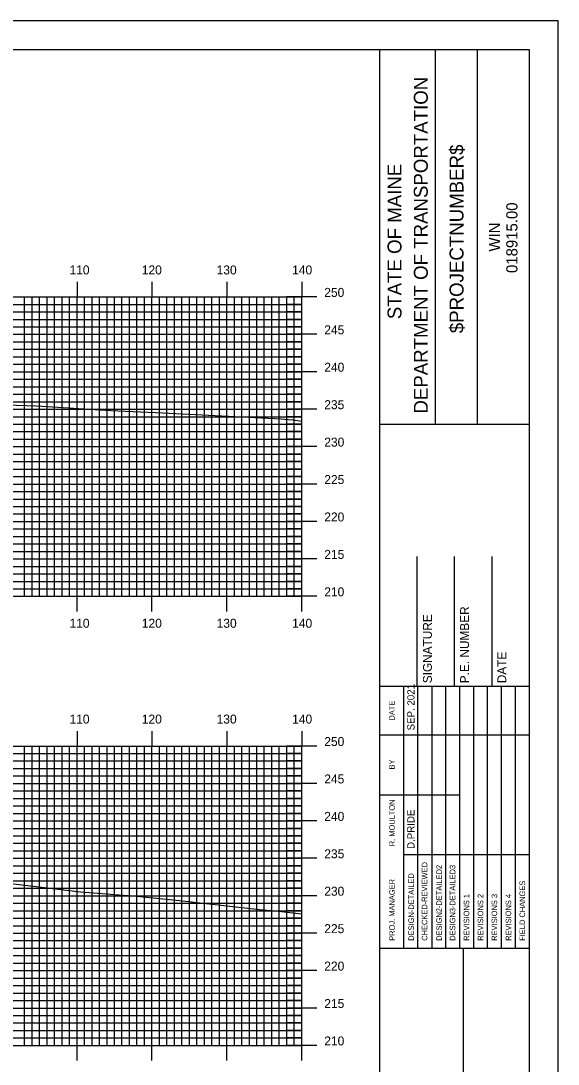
# Model space of a CAD drawing. Extents: x 1816489 to 1816833, y 442591 to 442811.
# Drawn here: x 1816757.6 to 1816829.3, y 442671.2 to 442810.5 of the extents above; entities that cross this region are included whole.
import ezdxf

# ---------------------------------------------------------------- set-up
doc = ezdxf.new("R2010")
doc.units = 0
for name, color, linetype in [('BORDER', 7, 'Continuous'), ('H_V ANNOTATION', 7, 'Continuous'), ('MAJOR', 7, 'Continuous'), ('MINOR', 7, 'Continuous'), ('PLOT BOUNDARY', 7, 'Continuous'), ('S_Roadway_Centerline', 7, 'Continuous')]:
    doc.layers.add(name, color=color, linetype=linetype)

msp = doc.modelspace()

# ---------------------------------------------------------------- linework, layer by layer
at = {"layer": 'BORDER'}
for p, q in [((1816805.47, 442596.67), (1816805.47, 442806.67)), ((1816812.93, 442756.66), (1816812.93, 442806.66)), ((1816818.52, 442756.66), (1816818.52, 442806.66)), ((1816805.47, 442756.65), (1816825.47, 442756.65)), ((1816810.47, 442721.67), (1816810.47, 442738.97)), ((1816815.47, 442721.67), (1816815.47, 442738.97)), ((1816820.47, 442721.67), (1816820.47, 442738.97)), ((1816805.47, 442721.67), (1816825.47, 442721.67)), ((1816805.47, 442686.67), (1816825.47, 442686.67)), ((1816816.66, 442616.67), (1816816.66, 442686.67))]:
    msp.add_line(p, q, dxfattribs=at)
msp.add_lwpolyline([(1816505.47, 442596.67), (1816825.47, 442596.67), (1816825.47, 442806.67), (1816505.47, 442806.67)], close=True, dxfattribs=at)
for points in [[(1816808.7, 442715.17), (1816808.7, 442721.67)], [(1816810.57, 442686.68), (1816810.57, 442721.67)], [(1816812.43, 442721.67), (1816812.43, 442686.68)], [(1816814.29, 442686.68), (1816814.29, 442721.67)], [(1816816.16, 442686.68), (1816816.16, 442721.67)], [(1816818.02, 442686.68), (1816818.02, 442721.67)], [(1816819.88, 442686.68), (1816819.88, 442721.67)], [(1816821.75, 442686.68), (1816821.75, 442721.67)], [(1816823.61, 442686.68), (1816823.61, 442721.67)], [(1816808.7, 442686.68), (1816808.7, 442720.26)], [(1816805.47, 442715.17), (1816825.47, 442715.17)], [(1816805.47, 442707.17), (1816808.7, 442707.17)], [(1816808.7, 442707.17), (1816816.16, 442707.17)], [(1816808.7, 442699.17), (1816825.47, 442699.17)]]:
    msp.add_lwpolyline(points, dxfattribs=at)
at = {"layer": 'MAJOR'}
for p, q in [((1816765.07, 442775.67), (1816765.07, 442773.67)), ((1816775.07, 442775.67), (1816775.07, 442773.67)), ((1816785.07, 442775.67), (1816785.07, 442773.67)), ((1816795.07, 442775.67), (1816795.07, 442773.67)), ((1816515.07, 442773.67), (1816795.07, 442773.67)), ((1816515.07, 442773.67), (1816795.07, 442773.67)), ((1816765.07, 442733.67), (1816765.07, 442773.67)), ((1816775.07, 442733.67), (1816775.07, 442773.67)), ((1816785.07, 442733.67), (1816785.07, 442773.67)), ((1816797.08, 442773.67), (1816793.07, 442773.67)), ((1816795.07, 442733.67), (1816795.07, 442773.67)), ((1816795.07, 442733.67), (1816795.07, 442773.67)), ((1816515.07, 442768.67), (1816795.07, 442768.67)), ((1816797.08, 442768.67), (1816793.07, 442768.67)), ((1816515.07, 442763.67), (1816795.07, 442763.67)), ((1816797.08, 442763.67), (1816793.07, 442763.67)), ((1816515.07, 442758.67), (1816795.07, 442758.67)), ((1816797.08, 442758.67), (1816793.07, 442758.67)), ((1816515.07, 442753.67), (1816795.07, 442753.67)), ((1816797.08, 442753.67), (1816793.07, 442753.67)), ((1816515.07, 442748.67), (1816795.07, 442748.67)), ((1816797.08, 442748.67), (1816793.07, 442748.67)), ((1816515.07, 442743.67), (1816795.07, 442743.67)), ((1816797.08, 442743.67), (1816793.07, 442743.67)), ((1816515.07, 442738.67), (1816795.07, 442738.67)), ((1816797.08, 442738.67), (1816793.07, 442738.67)), ((1816515.07, 442733.67), (1816795.07, 442733.67)), ((1816515.07, 442733.67), (1816795.07, 442733.67)), ((1816765.07, 442731.66), (1816765.07, 442733.67)), ((1816775.07, 442731.66), (1816775.07, 442733.67)), ((1816785.07, 442731.66), (1816785.07, 442733.67)), ((1816797.08, 442733.67), (1816793.07, 442733.67)), ((1816795.07, 442731.66), (1816795.07, 442733.67)), ((1816765.07, 442715.67), (1816765.07, 442713.67)), ((1816775.07, 442715.67), (1816775.07, 442713.67)), ((1816785.07, 442715.67), (1816785.07, 442713.67)), ((1816795.07, 442715.67), (1816795.07, 442713.67)), ((1816515.07, 442713.67), (1816795.07, 442713.67)), ((1816515.07, 442713.67), (1816795.07, 442713.67)), ((1816765.07, 442673.67), (1816765.07, 442713.67)), ((1816775.07, 442673.67), (1816775.07, 442713.67)), ((1816785.07, 442673.67), (1816785.07, 442713.67)), ((1816797.08, 442713.67), (1816793.07, 442713.67)), ((1816795.07, 442673.67), (1816795.07, 442713.67)), ((1816795.07, 442673.67), (1816795.07, 442713.67)), ((1816515.07, 442708.67), (1816795.07, 442708.67)), ((1816797.08, 442708.67), (1816793.07, 442708.67)), ((1816515.07, 442703.67), (1816795.07, 442703.67)), ((1816797.08, 442703.67), (1816793.07, 442703.67)), ((1816515.07, 442698.67), (1816795.07, 442698.67)), ((1816797.08, 442698.67), (1816793.07, 442698.67)), ((1816515.07, 442693.67), (1816795.07, 442693.67)), ((1816797.08, 442693.67), (1816793.07, 442693.67)), ((1816515.07, 442688.67), (1816795.07, 442688.67)), ((1816797.08, 442688.67), (1816793.07, 442688.67)), ((1816515.07, 442683.67), (1816795.07, 442683.67)), ((1816797.08, 442683.67), (1816793.07, 442683.67)), ((1816515.07, 442678.67), (1816795.07, 442678.67)), ((1816797.08, 442678.67), (1816793.07, 442678.67)), ((1816515.07, 442673.67), (1816795.07, 442673.67)), ((1816515.07, 442673.67), (1816795.07, 442673.67)), ((1816765.07, 442671.66), (1816765.07, 442673.67)), ((1816775.07, 442671.66), (1816775.07, 442673.67)), ((1816785.07, 442671.66), (1816785.07, 442673.67)), ((1816797.08, 442673.67), (1816793.07, 442673.67)), ((1816795.07, 442671.66), (1816795.07, 442673.67))]:
    msp.add_line(p, q, dxfattribs=at)
at = {"layer": 'MINOR'}
for p, q in [((1816758.07, 442733.67), (1816758.07, 442773.67)), ((1816759.07, 442733.67), (1816759.07, 442773.67)), ((1816760.07, 442733.67), (1816760.07, 442773.67)), ((1816761.07, 442733.67), (1816761.07, 442773.67)), ((1816762.07, 442733.67), (1816762.07, 442773.67)), ((1816763.07, 442733.67), (1816763.07, 442773.67)), ((1816764.07, 442733.67), (1816764.07, 442773.67)), ((1816766.07, 442733.67), (1816766.07, 442773.67)), ((1816767.07, 442733.67), (1816767.07, 442773.67)), ((1816768.07, 442733.67), (1816768.07, 442773.67)), ((1816769.07, 442733.67), (1816769.07, 442773.67)), ((1816770.07, 442733.67), (1816770.07, 442773.67)), ((1816771.07, 442733.67), (1816771.07, 442773.67)), ((1816772.07, 442733.67), (1816772.07, 442773.67)), ((1816773.07, 442733.67), (1816773.07, 442773.67)), ((1816774.07, 442733.67), (1816774.07, 442773.67)), ((1816776.07, 442733.67), (1816776.07, 442773.67)), ((1816777.07, 442733.67), (1816777.07, 442773.67)), ((1816778.07, 442733.67), (1816778.07, 442773.67)), ((1816779.07, 442733.67), (1816779.07, 442773.67)), ((1816780.07, 442733.67), (1816780.07, 442773.67)), ((1816781.07, 442733.67), (1816781.07, 442773.67)), ((1816782.07, 442733.67), (1816782.07, 442773.67)), ((1816783.07, 442733.67), (1816783.07, 442773.67)), ((1816784.07, 442733.67), (1816784.07, 442773.67)), ((1816786.07, 442733.67), (1816786.07, 442773.67)), ((1816787.07, 442733.67), (1816787.07, 442773.67)), ((1816788.07, 442733.67), (1816788.07, 442773.67)), ((1816789.07, 442733.67), (1816789.07, 442773.67)), ((1816790.07, 442733.67), (1816790.07, 442773.67)), ((1816791.07, 442733.67), (1816791.07, 442773.67)), ((1816792.07, 442733.67), (1816792.07, 442773.67)), ((1816793.07, 442733.67), (1816793.07, 442773.67)), ((1816794.07, 442733.67), (1816794.07, 442773.67)), ((1816515.07, 442772.67), (1816795.07, 442772.67)), ((1816515.07, 442771.67), (1816795.07, 442771.67)), ((1816795.07, 442772.67), (1816793.07, 442772.67)), ((1816795.07, 442771.67), (1816793.07, 442771.67)), ((1816515.07, 442770.67), (1816795.07, 442770.67)), ((1816795.07, 442770.67), (1816793.07, 442770.67)), ((1816515.07, 442769.67), (1816795.07, 442769.67)), ((1816795.07, 442769.67), (1816793.07, 442769.67)), ((1816515.07, 442767.67), (1816795.07, 442767.67)), ((1816795.07, 442767.67), (1816793.07, 442767.67)), ((1816515.07, 442766.67), (1816795.07, 442766.67)), ((1816795.07, 442766.67), (1816793.07, 442766.67)), ((1816515.07, 442765.67), (1816795.07, 442765.67)), ((1816515.07, 442764.67), (1816795.07, 442764.67)), ((1816795.07, 442765.67), (1816793.07, 442765.67)), ((1816795.07, 442764.67), (1816793.07, 442764.67)), ((1816515.07, 442762.67), (1816795.07, 442762.67)), ((1816515.07, 442761.67), (1816795.07, 442761.67)), ((1816795.07, 442762.67), (1816793.07, 442762.67)), ((1816795.07, 442761.67), (1816793.07, 442761.67)), ((1816515.07, 442760.67), (1816795.07, 442760.67)), ((1816795.07, 442760.67), (1816793.07, 442760.67)), ((1816515.07, 442759.67), (1816795.07, 442759.67)), ((1816795.07, 442759.67), (1816793.07, 442759.67)), ((1816515.07, 442757.67), (1816795.07, 442757.67)), ((1816795.07, 442757.67), (1816793.07, 442757.67)), ((1816515.07, 442756.67), (1816795.07, 442756.67)), ((1816795.07, 442756.67), (1816793.07, 442756.67)), ((1816515.07, 442755.67), (1816795.07, 442755.67)), ((1816515.07, 442754.67), (1816795.07, 442754.67)), ((1816795.07, 442755.67), (1816793.07, 442755.67)), ((1816795.07, 442754.67), (1816793.07, 442754.67)), ((1816515.07, 442752.67), (1816795.07, 442752.67)), ((1816795.07, 442752.67), (1816793.07, 442752.67)), ((1816515.07, 442751.67), (1816795.07, 442751.67)), ((1816515.07, 442750.67), (1816795.07, 442750.67)), ((1816795.07, 442751.67), (1816793.07, 442751.67)), ((1816795.07, 442750.67), (1816793.07, 442750.67)), ((1816515.07, 442749.67), (1816795.07, 442749.67)), ((1816795.07, 442749.67), (1816793.07, 442749.67)), ((1816515.07, 442747.67), (1816795.07, 442747.67)), ((1816795.07, 442747.67), (1816793.07, 442747.67)), ((1816515.07, 442746.67), (1816795.07, 442746.67)), ((1816795.07, 442746.67), (1816793.07, 442746.67)), ((1816515.07, 442745.67), (1816795.07, 442745.67)), ((1816795.07, 442745.67), (1816793.07, 442745.67)), ((1816515.07, 442744.67), (1816795.07, 442744.67)), ((1816795.07, 442744.67), (1816793.07, 442744.67)), ((1816515.07, 442742.67), (1816795.07, 442742.67)), ((1816795.07, 442742.67), (1816793.07, 442742.67)), ((1816515.07, 442741.67), (1816795.07, 442741.67)), ((1816795.07, 442741.67), (1816793.07, 442741.67)), ((1816515.07, 442740.67), (1816795.07, 442740.67)), ((1816515.07, 442739.67), (1816795.07, 442739.67)), ((1816795.07, 442740.67), (1816793.07, 442740.67)), ((1816795.07, 442739.67), (1816793.07, 442739.67)), ((1816515.07, 442737.67), (1816795.07, 442737.67)), ((1816515.07, 442736.67), (1816795.07, 442736.67)), ((1816795.07, 442737.67), (1816793.07, 442737.67)), ((1816795.07, 442736.67), (1816793.07, 442736.67)), ((1816515.07, 442735.67), (1816795.07, 442735.67)), ((1816795.07, 442735.67), (1816793.07, 442735.67)), ((1816515.07, 442734.67), (1816795.07, 442734.67)), ((1816795.07, 442734.67), (1816793.07, 442734.67)), ((1816758.07, 442673.67), (1816758.07, 442713.67)), ((1816759.07, 442673.67), (1816759.07, 442713.67)), ((1816760.07, 442673.67), (1816760.07, 442713.67)), ((1816761.07, 442673.67), (1816761.07, 442713.67)), ((1816762.07, 442673.67), (1816762.07, 442713.67)), ((1816763.07, 442673.67), (1816763.07, 442713.67)), ((1816764.07, 442673.67), (1816764.07, 442713.67)), ((1816766.07, 442673.67), (1816766.07, 442713.67)), ((1816767.07, 442673.67), (1816767.07, 442713.67)), ((1816768.07, 442673.67), (1816768.07, 442713.67)), ((1816769.07, 442673.67), (1816769.07, 442713.67)), ((1816770.07, 442673.67), (1816770.07, 442713.67)), ((1816771.07, 442673.67), (1816771.07, 442713.67)), ((1816772.07, 442673.67), (1816772.07, 442713.67)), ((1816773.07, 442673.67), (1816773.07, 442713.67)), ((1816774.07, 442673.67), (1816774.07, 442713.67)), ((1816776.07, 442673.67), (1816776.07, 442713.67)), ((1816777.07, 442673.67), (1816777.07, 442713.67)), ((1816778.07, 442673.67), (1816778.07, 442713.67)), ((1816779.07, 442673.67), (1816779.07, 442713.67)), ((1816780.07, 442673.67), (1816780.07, 442713.67)), ((1816781.07, 442673.67), (1816781.07, 442713.67)), ((1816782.07, 442673.67), (1816782.07, 442713.67)), ((1816783.07, 442673.67), (1816783.07, 442713.67)), ((1816784.07, 442673.67), (1816784.07, 442713.67)), ((1816786.07, 442673.67), (1816786.07, 442713.67)), ((1816787.07, 442673.67), (1816787.07, 442713.67)), ((1816788.07, 442673.67), (1816788.07, 442713.67)), ((1816789.07, 442673.67), (1816789.07, 442713.67)), ((1816790.07, 442673.67), (1816790.07, 442713.67)), ((1816791.07, 442673.67), (1816791.07, 442713.67)), ((1816792.07, 442673.67), (1816792.07, 442713.67)), ((1816793.07, 442673.67), (1816793.07, 442713.67)), ((1816794.07, 442673.67), (1816794.07, 442713.67)), ((1816515.07, 442712.67), (1816795.07, 442712.67)), ((1816515.07, 442711.67), (1816795.07, 442711.67)), ((1816795.07, 442712.67), (1816793.07, 442712.67)), ((1816795.07, 442711.67), (1816793.07, 442711.67)), ((1816515.07, 442710.67), (1816795.07, 442710.67)), ((1816795.07, 442710.67), (1816793.07, 442710.67)), ((1816515.07, 442709.67), (1816795.07, 442709.67)), ((1816795.07, 442709.67), (1816793.07, 442709.67)), ((1816515.07, 442707.67), (1816795.07, 442707.67)), ((1816795.07, 442707.67), (1816793.07, 442707.67)), ((1816515.07, 442706.67), (1816795.07, 442706.67)), ((1816795.07, 442706.67), (1816793.07, 442706.67)), ((1816515.07, 442705.67), (1816795.07, 442705.67)), ((1816515.07, 442704.67), (1816795.07, 442704.67)), ((1816795.07, 442705.67), (1816793.07, 442705.67)), ((1816795.07, 442704.67), (1816793.07, 442704.67)), ((1816515.07, 442702.67), (1816795.07, 442702.67)), ((1816515.07, 442701.67), (1816795.07, 442701.67)), ((1816795.07, 442702.67), (1816793.07, 442702.67)), ((1816795.07, 442701.67), (1816793.07, 442701.67)), ((1816515.07, 442700.67), (1816795.07, 442700.67)), ((1816795.07, 442700.67), (1816793.07, 442700.67)), ((1816515.07, 442699.67), (1816795.07, 442699.67)), ((1816795.07, 442699.67), (1816793.07, 442699.67)), ((1816515.07, 442697.67), (1816795.07, 442697.67)), ((1816795.07, 442697.67), (1816793.07, 442697.67)), ((1816515.07, 442696.67), (1816795.07, 442696.67)), ((1816795.07, 442696.67), (1816793.07, 442696.67)), ((1816515.07, 442695.67), (1816795.07, 442695.67)), ((1816795.07, 442695.67), (1816793.07, 442695.67)), ((1816515.07, 442694.67), (1816795.07, 442694.67)), ((1816795.07, 442694.67), (1816793.07, 442694.67)), ((1816515.07, 442692.67), (1816795.07, 442692.67)), ((1816795.07, 442692.67), (1816793.07, 442692.67)), ((1816515.07, 442691.67), (1816795.07, 442691.67)), ((1816515.07, 442690.67), (1816795.07, 442690.67)), ((1816795.07, 442691.67), (1816793.07, 442691.67)), ((1816795.07, 442690.67), (1816793.07, 442690.67)), ((1816515.07, 442689.67), (1816795.07, 442689.67)), ((1816795.07, 442689.67), (1816793.07, 442689.67)), ((1816515.07, 442687.67), (1816795.07, 442687.67)), ((1816515.07, 442686.67), (1816795.07, 442686.67)), ((1816795.07, 442687.67), (1816793.07, 442687.67)), ((1816795.07, 442686.67), (1816793.07, 442686.67)), ((1816515.07, 442685.67), (1816795.07, 442685.67)), ((1816795.07, 442685.67), (1816793.07, 442685.67)), ((1816515.07, 442684.67), (1816795.07, 442684.67)), ((1816795.07, 442684.67), (1816793.07, 442684.67)), ((1816515.07, 442682.67), (1816795.07, 442682.67)), ((1816795.07, 442682.67), (1816793.07, 442682.67)), ((1816515.07, 442681.67), (1816795.07, 442681.67)), ((1816795.07, 442681.67), (1816793.07, 442681.67)), ((1816515.07, 442680.67), (1816795.07, 442680.67)), ((1816515.07, 442679.67), (1816795.07, 442679.67)), ((1816795.07, 442680.67), (1816793.07, 442680.67)), ((1816795.07, 442679.67), (1816793.07, 442679.67)), ((1816515.07, 442677.67), (1816795.07, 442677.67)), ((1816515.07, 442676.67), (1816795.07, 442676.67)), ((1816795.07, 442677.67), (1816793.07, 442677.67)), ((1816795.07, 442676.67), (1816793.07, 442676.67)), ((1816515.07, 442675.67), (1816795.07, 442675.67)), ((1816795.07, 442675.67), (1816793.07, 442675.67)), ((1816515.07, 442674.67), (1816795.07, 442674.67)), ((1816795.07, 442674.67), (1816793.07, 442674.67))]:
    msp.add_line(p, q, dxfattribs=at)
at = {"layer": 'PLOT BOUNDARY'}
msp.add_lwpolyline([(1816489.29, 442590.55), (1816829.29, 442590.55), (1816829.29, 442810.55), (1816489.29, 442810.55)], close=True, dxfattribs=at)
at = {"layer": 'S_Roadway_Centerline'}
for points in [[(1816684.67, 442763.38), (1816688.54, 442763.29), (1816690.96, 442763.15), (1816693.6, 442762.92), (1816696.97, 442762.92), (1816709.06, 442761.95), (1816724.24, 442761.08), (1816725.42, 442761), (1816730.22, 442760.64), (1816740.26, 442759.88), (1816741.95, 442759.77), (1816744.76, 442759.61), (1816759.65, 442759.11), (1816769.56, 442758.48), (1816776.48, 442758.16), (1816792.33, 442757.36), (1816793.3, 442757.27), (1816793.89, 442757.24), (1816795.07, 442757.09)], [(1816678.58, 442701.01), (1816690.94, 442700.24), (1816693.32, 442700.75), (1816695.45, 442699.98), (1816698.67, 442699.81), (1816701.63, 442699.46), (1816703.64, 442699.27), (1816704.72, 442699.13), (1816716.67, 442698.53), (1816721.45, 442698.19), (1816724.58, 442698.06), (1816734.94, 442697.24), (1816738.44, 442696.94), (1816739.5, 442696.86), (1816752.33, 442695.86), (1816756.62, 442695.24), (1816765.53, 442694.2), (1816772.99, 442693.6), (1816778.73, 442693.04), (1816789.41, 442691.82), (1816791.91, 442691.6), (1816795.07, 442691.25)]]:
    msp.add_lwpolyline(points, dxfattribs=at)

# ---------------------------------------------------------------- texts
at = {"layer": 'BORDER'}
for s, height, p in [('DEPARTMENT OF TRANSPORTATION', 1.8635, (1816811.89, 442758.08)), ('$PROJECTNUMBER$', 1.8635, (1816816.66, 442768.82)), ('STATE OF MAINE', 1.8635, (1816808.38, 442770.69)), ('018915.00', 1.491, (1816823.86, 442776.86)), ('WIN', 1.491, (1816821.55, 442779.73)), ('SIGNATURE', 1.181, (1816812.43, 442722.06)), ('P.E. NUMBER', 1.1811, (1816817.39, 442722.06)), ('DATE', 1.181, (1816822.36, 442722.06)), ('SEP. 2021', 0.969, (1816810.12, 442715.76)), ('DATE', 0.743, (1816807.48, 442717.08)), ('BY', 0.743, (1816807.48, 442710.54)), ('R. MOULTON', 0.745, (1816807.48, 442700.28)), ('D.PRIDE', 0.969, (1816810.12, 442699.92)), ('CHECKED-REVIEWED', 0.7455, (1816811.83, 442687.65)), ('DESIGN2-DETAILED2', 0.7455, (1816813.77, 442687.65)), ('DESIGN3-DETAILED3', 0.7455, (1816815.56, 442687.65)), ('DESIGN-DETAILED', 0.7455, (1816810.05, 442687.65)), ('PROJ. MANAGER', 0.7455, (1816807.48, 442687.65)), ('FIELD CHANGES', 0.7455, (1816824.88, 442687.65)), ('REVISIONS 1', 0.7455, (1816817.43, 442687.65)), ('REVISIONS 2', 0.7455, (1816819.29, 442687.65)), ('REVISIONS 3', 0.7455, (1816821.15, 442687.65)), ('REVISIONS 4', 0.7455, (1816823.02, 442687.65))]:
    msp.add_text(s, height=height, rotation=90, dxfattribs=at).set_placement(p)
at = {"layer": 'H_V ANNOTATION'}
for s, p in [('110', (1816764.06, 442776.67)), ('120', (1816773.71, 442776.67)), ('130', (1816783.7, 442776.67)), ('140', (1816793.78, 442776.67)), ('250', (1816798.07, 442773.67)), ('245', (1816798.07, 442768.67)), ('240', (1816798.07, 442763.67)), ('235', (1816798.07, 442758.67)), ('230', (1816798.07, 442753.67)), ('225', (1816798.07, 442748.67)), ('220', (1816798.07, 442743.67)), ('215', (1816798.07, 442738.67)), ('210', (1816798.07, 442733.67)), ('110', (1816764.06, 442729.47)), ('120', (1816773.71, 442729.47)), ('130', (1816783.7, 442729.47)), ('140', (1816793.78, 442729.47)), ('110', (1816764.06, 442716.67)), ('120', (1816773.71, 442716.67)), ('130', (1816783.7, 442716.67)), ('140', (1816793.78, 442716.67)), ('250', (1816798.07, 442713.67)), ('245', (1816798.07, 442708.67)), ('240', (1816798.07, 442703.67)), ('235', (1816798.07, 442698.67)), ('230', (1816798.07, 442693.67)), ('225', (1816798.07, 442688.67)), ('220', (1816798.07, 442683.67)), ('215', (1816798.07, 442678.67)), ('210', (1816798.07, 442673.67))]:
    msp.add_text(s, height=1.2, dxfattribs=at).set_placement(p)

doc.saveas('drawing.dxf')
